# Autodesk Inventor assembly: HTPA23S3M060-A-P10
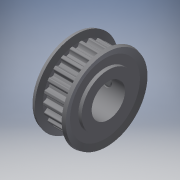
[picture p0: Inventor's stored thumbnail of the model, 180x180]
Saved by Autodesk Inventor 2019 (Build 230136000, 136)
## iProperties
Category: PARTsolutions
Company: MISUMI
Created: 2022-11
Part Number: HTPA23S3M060-A-P10
Catalog Web Link: www.cadenas.de
Description: HTPA__S3M060, HTPA__S3M100, HTPA__S3M150, HTPB__S3M060, HTPB__S3M100, HTPB__S3M150, HTPK__S3M060, HTPK__S3M100, HTPK__S3M150, HTPN__S3M060, HTPN__S3M100, HTPN__
Vendor: MISUMI
Document SubType Name: Assembly
Designer: psAdmin
Manufacturer: MISUMI
Mass: 2.68562 g
Surface Area: 25.9941 cm^2
Volume: 2.68562 cm^3
Density: 1 g/cm^3
Title: HTPA23S3M060-A-P10
Author: Cadenas PARTsolutions
Comments: High Torque Timing Pulleys S3M Type
PSOL_IDENT_0: {$CADENAS_DATA/23d-libs/misumi/metric/51_timing_pulleys/htpk_s3m_asmtab.prj},844 {VTYP=3D},{STYP=ASS
PSOL_IDENT_1: TAB},{NB=HTPA23S3M060-A-P10},{LINA=HTPA23S3M060-A-P10},{NN=HTPA__S3M060, HTPA__S3M100, HTPA__S3M150,
PSOL_IDENT_2: HTPB__S3M060, HTPB__S3M100, HTPB__S3M150, HTPK__S3M060, HTPK__S3M100, HTPK__S3M150, HTPN__S3M060, H
PSOL_IDENT_3: TPN__S3M100, HTPN__S3M150, HTPT__S3M060, HTPT__S3M100, HTPT__S3M150, HTPM__S3M060, HTPM__S3M100, HTP
PSOL_IDENT_4: M__S3M150, HTPP__S3M060, HTPP__S3M100, HTPP__S3M150, HTPS__S3M060, HTPS__S3M100, KHTPA__S3M060, KHTP
PSOL_IDENT_5: A__S3M100, KHTPA__S3M150, KHTPK__S3M060, KHTPK__S3M100, KHTPK__S3M150},{DATE=28.10.2022 00:10:07},{G
PSOL_IDENT_6: EOMDATE=15.11.2021 05:07:15},{VERSION=},{LINEID=330},{WBVAR=MATP,ST,TNW,PS,SBS,DD,Z,J,Q,R,S,T,ALT1,A
PSOL_IDENT_7: LT2,M,QSC,QFC,QTC,ALT3,K,KSC,KFC,KTC,ALT4,ZM,ZSC,ZFC,ZTC,ALT5,ALT6,ALT7,FC,ALT8,SRG,ALT9,BTC,TL,ALT1
PSOL_IDENT_8: 0,TPC,ALT11,BC,ALT12,SLH,ALT13,BN},{WBNUMERIC=DD,Z,J,Q,R,S,T,QSC,QFC,QTC,K,KSC,KFC,KTC,ZSC,ZFC,ZTC,F
PSOL_IDENT_9: C,SRG,BTC,TL,BC,SLH,BN}  {NB=HTPA23S3M060-A-P10},{LINA=HTPA23S3M060-A-P10},{KT=DUMMY},{PN=HTPA23S3M0
PSOL_IDENT_10: 60-A-P10},{TYPE=HTPA},{MATP=A2017},{MATPALG='A2017','Aluminum Alloy 2000 series','S45C','1045 Carbon
PSOL_IDENT_11: Steel Equivalent','SUS304','304 Stainless Steel','A6000','6000 Series Aluminum Alloy'},{ST=CA},{STA
PSOL_IDENT_12: LG= 'CA','Clear Anodize','BA','Black Anodize','HAT','Hard Clear Anodize','ENP','Electroless Nickel P
PSOL_IDENT_13: lating' },{NT=23},{TNW=S3M060},{TNWALG= 'S3M060','S3M100','S3M150'    },{BW=6},{PS=A},{PSALG='A','B'
PSOL_IDENT_14: },{SBS=P},{SBSALG= 'H','Round Hole','P','Round Hole + Tap','V','Stepped Hole', 'Y','Both Ends Steppe
PSOL_IDENT_15: d Hole','WB', 'Double Stepped Hole' },{SHSA= 'H','Round Hole','P','Round Hole + Tap','V','Stepped Ho
PSOL_IDENT_16: le', 'Y','Both Ends Stepped Hole','WB', 'Double Stepped Hole' },{SHSB= 'H','Round Hole','P','Round H
PSOL_IDENT_17: ole + Tap','V','Stepped Hole','F','Stepped Hole (Counterbore holes on the boss side)'},{SHSK= '',''
PSOL_IDENT_18: },{SBSPN=-P10},{DD=10.00},{DDALG=[4:4/1],4.5,[5:6/1],6.35,[7:10/1]},{DDHA=[4:4/1],4.5,[5:6/1],6.35,[
PSOL_IDENT_19: 7:12/1]},{DDHBK=0},{DDPA=[4:4/1],4.5,[5:6/1],6.35,[7:10/1]},{DDPBK=0},{DDNA=[8:8/1],[10:11/1]},{DDNB
PSOL_IDENT_20: K=0},{DDNK=0},{DDCA=[10:10/1]},{DDCBK=0},{DDVA=[4:4/1],4.5,[5:6/1],6.35,[7:10/1]},{DDVF=[4:4/1],4.5,
PSOL_IDENT_21: [5:6/1],6.35,[7:8/1]},{DDY=[4:10/1]},{DDWB=[4:8/1]},{Z=0},{ZALG=[0]},{ZQRMIN=12},{ZAMAX=12},{ZBMAX=1
PSOL_IDENT_22: 0},{DDZ=10},{J=0.0},{JALG=[0]},{JMAX=9},{JMIN=2},{JPN=},{QRMAX=12},{QRMIN=12},{WBRMAX=-2.00},{WBQMIN=
PSOL_IDENT_23: 14},{Q=0},{QALG=[0]},{QPN=},{R=0},{RALG=[0]},{S=0.0},{SALG=[0]},{SPN=},{SMAX=5},{T=0.0},{TALG=[0]},{
PSOL_IDENT_24: TPN=},{TMAX=8},{A=7},{W=11},{L=0},{PD=21.96},{OD=21.20},{D=0},{DALG=25},{DE=16},{F=25},{E=16},{BBK=0
PSOL_IDENT_25: .000},{TTK=0.0},{TT=1},{ANG=125.217391},{WL=11},{ALT1=},{ALT1ALG= '','w/o KC90 (Set Screw Angle)','K
PSOL_IDENT_26: C90','with KC90 (Set Screw Angle)' },{ALT1PN=},{ALT2=},{ALT2ALG= '','Not applicable' },{M=N/A},{MALG=
PSOL_IDENT_27: 'N/A' },{MFTALG= 'N/A' },{MSALG= 'N/A' },{M3D=0.000},{KDML=0},{ML=0},{MUL=0},{PITCH=0},{QSC=0.0},{Q
PSOL_IDENT_28: SCALG=0},{QFC=0.0},{QFCALG=0},{QTC=0.0},{QTCALG=0},{QPCDMIN=0},{QPCDMINALG=0},{QPCDMAX=12},{ALT2PN=}
PSOL_IDENT_29: ,{ALT3=},{ALT3ALG= '','Not applicable' },{K=0.0},{KALG=0},{KMIN=4},{KFTMAX=0.0},{KSMAX=0.0},{KSC=0.0
PSOL_IDENT_30: },{KSCALG=0},{KFC=0.0},{KFCALG=0},{KTC=0.0},{KTCALG=0},{KPCDMIN=14},{KPCDMINALG=14},{KPCDMAX=12},{KS
PSOL_IDENT_31: CMIN=14.0},{KSCMINALG=14},{ALT3PN=},{ALT4=},{ALT4ALG= '','Not applicable' },{ALT4MIN=20.5},{ALT4MAX=
PSOL_IDENT_32: 5.5},{ZM=N/A},{ZMALG= 'N/A' },{ZMSALG= 'N/A' },{ZMFTALG= 'N/A' },{ZMDD1=0.0},{ZMDD2=0.0},{ZMHH=0.0},
PSOL_IDENT_33: {ZSC=0.0},{ZSCALG=[0]},{ZFC=0.0},{ZFCALG=[0]},{ZTC=0.0},{ZTCALG=[0]},{ZPCDMIN=0},{ZPCDMINALG=0},{ZPC
PSOL_IDENT_34: DMAX=12},{ALT4PN=},{ALT5=},{ALT5ALG= '','Flange Attached','NFC','with NFC (Flange not Attached)' },{
PSOL_IDENT_35: ALT5PN=},{ALT6=},{ALT6ALG= '','w/o Flange Attached on One Side Only','RFC','with RFC (Flange Attache
PSOL_IDENT_36: d on The Boss Side Only)','LFC','with LFC (Flange Attached on The Opposite Side Only)' },{ALT6PN=},{
PSOL_IDENT_37: ALT7=},{ALT7ALG= '','w/o FC (Flange Cut)','FC','with FC (Flange Cut)' },{FC=0.0},{FCALG=0},{FCMIN=22
PSOL_IDENT_38: .5},{FCMAX=23.0},{ALT7PN=},{ALT8=},{ALT8ALG= '','Not applicable' },{ALT8ALGALG=12},{ALT8DD2=0},{ALT8
PSOL_IDENT_39: MM=0},{ALT8NN=0},{QC=0},{KC=0},{ZC=0},{SRG=0.0},{SRGALG=[0]},{SRGMAX1=0},{SRGMAX=0},{DD2=0.0},{MM=0.
PSOL_IDENT_40: 00},{NN=0.00},{ALT8PN=},{ALT9ALG= '','w/o BTC (Taper for Bearing Holder)','BTC','with BTC (Taper for
PSOL_IDENT_41: Bearing Holder)' },{ALT9=},{BTC9=11},{TL9=1},{BTC=0},{BTCALG=[0]},{TL=0.0},{TLALG=0},{TLMIN=1.0},{T
PSOL_IDENT_42: LMAX=-11.5},{BTCL=0},{BTCD=0},{BTCDALG=16.000},{ALT9PN=},{WLBCTL=11},{ALT10=},{ALT10ALG= '','w/o TPC
PSOL_IDENT_43: (Tapped Hole Dimension)','TPC','with TPC (Tapped Hole Dimension)' },{TPC=N/A},{TPCALG= 'N/A' },{TPC
PSOL_IDENT_44: M=4},{ALT10PN=},{ALT11=},{ALT11ALG= '','Not applicable' },{BC=0.0},{BCALG=0},{BCMIN=7},{BCMAX=-11.5}
PSOL_IDENT_45: ,{BCPLANE=5.5},{M1WBC=5.5},{ALT11PN=},{ALT12=},{ALT12ALG= '','w/o SLH (Set Screw Length)','SLH','wit
PSOL_IDENT_46: h SLH (Set Screw Length)' },{SLH=0},{SLHALG=[0]},{ALT12PN=},{AC=M4x3},{M1=4},{M1L=3},{TAP=0.000},{KY
PSOL_IDENT_47: Y=5},{KTT=5.6},{PLANE=11},{ALT13=},{ALT13ALG= '', 'Not applicable' },{BN=0.0},{BNALG=0},{BNMIN=-10.5
PSOL_IDENT_48: },{BNMAX=-1.0},{ALT13PN=},{PPATH=htpk_s3m/htpa_s3m_asmtpl.prj}
NB: HTPA23S3M060-A-P10
NN: 0
NT: 23
NBSYN: $PN.
LINA: HTPA23S3M060-A-P10
CATALOG: Misumi
PN: HTPA23S3M060-A-P10
MATP: Aluminum Alloy 2000 series
ST: Clear Anodize
TNW: S3M060
BW: 6
PS: A
SBS: Round Hole + Tap
DD: 10
Z: 0
J: 0
Q: 0
R: 0
S: 0
T: 0
A: 7
W: 11
L: 0
PD: 21.96
OD: 21.2
D: 0
F: 25
E: 16
TT: 1
ALT1: w/o KC90 (Set Screw Angle)
ALT2: Not applicable
M: N/A
QSC: 0
QFC: 0
QTC: 0
ALT3: Not applicable
K: 0
KSC: 0
KFC: 0
KTC: 0
ALT4: Not applicable
ZM: N/A
ZMDD1: 0
ZMDD2: 0
ZMHH: 0
ZSC: 0
ZFC: 0
ZTC: 0
ALT5: Flange Attached
ALT6: w/o Flange Attached on One Side Only
ALT7: w/o FC (Flange Cut)
FC: 0
ALT8: Not applicable
SRG: 0
DD2: 0
MM: 0
ALT9: w/o BTC (Taper for Bearing Holder)
BTC: 0
TL: 0
BTCL: 0
BTCD: 0
ALT10: w/o TPC (Tapped Hole Dimension)
TPC: N/A
ALT11: Not applicable
BC: 0
ALT12: w/o SLH (Set Screw Length)
SLH: 0
AC: M4x3
ALT13: Not applicable
BN: 0
SUPPLIER: MISUMI
ARTICLENO: HTPA23S3M060-A-P10
BOMINFO: HTPA23S3M060-A-P10
CREATOR: CADENAS GmbH
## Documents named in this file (3)
- e:\temp\worker_COMMON_15\temp\tmp_8944_128_K1495\format_0\HTPA23S3M060-A-P10.iam
- e:\temp\worker_COMMON_15\temp\tmp_8944_128_K1495\format_0\HTPA23S3M060-A-P10_b.ipt
- e:\temp\worker_COMMON_15\temp\tmp_8944_128_K1495\format_0\SET-SCREW4-3.ipt
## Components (3 placed, 2 different names)
1. HTPA23S3M060-A-P10_b:1 — to_screw1_XY@1 <-> CP_XY@2, to_screw1_Z@1 <-> CP_Z@2, to_screw1_YZ@1 <-> CP_YZ@2, to_screw2_XY@1 <-> CP_XY@3, to_screw2_Z@1 <-> CP_Z@3, to_screw2_YZ@1 <-> CP_YZ@3
2. SET-SCREW4-3:1 — to_screw1_XY@1 <-> CP_XY@2, to_screw1_Z@1 <-> CP_Z@2, to_screw1_YZ@1 <-> CP_YZ@2
3. SET-SCREW4-3:2 — to_screw2_XY@1 <-> CP_XY@3, to_screw2_Z@1 <-> CP_Z@3, to_screw2_YZ@1 <-> CP_YZ@3
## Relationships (6: Mate 4, Angle 2)
- to_screw1_XY@1 <-> CP_XY@2 [Mate]: HTPA23S3M060-A-P10_b:1 ↔ SET-SCREW4-3:1
- to_screw1_Z@1 <-> CP_Z@2 [Mate]: HTPA23S3M060-A-P10_b:1 ↔ SET-SCREW4-3:1
- to_screw1_YZ@1 <-> CP_YZ@2 [Angle]: HTPA23S3M060-A-P10_b:1 ↔ SET-SCREW4-3:1
- to_screw2_XY@1 <-> CP_XY@3 [Mate]: HTPA23S3M060-A-P10_b:1 ↔ SET-SCREW4-3:2
- to_screw2_Z@1 <-> CP_Z@3 [Mate]: HTPA23S3M060-A-P10_b:1 ↔ SET-SCREW4-3:2
- to_screw2_YZ@1 <-> CP_YZ@3 [Angle]: HTPA23S3M060-A-P10_b:1 ↔ SET-SCREW4-3:2
